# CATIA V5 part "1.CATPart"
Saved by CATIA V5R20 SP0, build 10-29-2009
Part number: Part1
Material "Steel": density 7860 kg/m3, Young's modulus 2e+11 Pa, Poisson ratio 0.266, thermal expansion 1.17e-05 1/K
Bounding box of the stored display mesh (mm): x -9.62 to 87.685, y -20.777 to 20.777, z -26.228 to 2
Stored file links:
  E:\Ehsan\Amoozesh\CATIA\CATIA Course\Advanced\Videos\Session-14\1.CATPart
  D:\CATIA V5R20\B20\intel_a\startup\materials\Catalog.CATMaterial
  D:\CATIA V5R20\B20\intel_a\resources\graphic\figures\CATIA_EnvironmentMap_Potsdamer_512x512.jpg
  D:\CATIA V5R20\B20\intel_a\resources\graphic\figures\CATIA_EnvironmentMap_DSBlack_512x512.jpg
  D:\CATIA V5R20\B20\intel_a\resources\graphic\figures\CATIA_EnvironmentMap_Default_512x512.jpg
  D:\CATIA V5R20\B20\intel_a\resources\graphic\figures\CATIA_EnvironmentMap_DSYellow_512x512.jpg
  D:\CATIA V5R20\B20\intel_a\resources\graphic\figures\CATIA_EnvironmentMap_DSRed_512x512.jpg
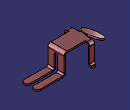
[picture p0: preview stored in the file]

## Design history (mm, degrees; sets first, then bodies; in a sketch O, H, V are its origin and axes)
SheetMetalParameters1: Thickness 2, BendRadius 2, KFactor 0.325257 {= log(min(100,max(20*SheetMetalParameters1.BendRadius,SheetMetalParameters1.Thickness)/SheetMetalParameters1.Thickness))/log(100)/2}, ReliefRadialLength 1, ReliefAxialLength 2, MinimumBendRadius 0
Body1 (main body), material "Steel"
  Sketch1 on xy-plane, origin (0, 0, 0), H (0, 1, 0), V (-1, 0, 0)
    arc A1 centre (0, 0) radius 12.5 from (3.5, -12) to (-3.5, -12) ccw
    point P1 (40, -19.25)
    point P2 (-3.5, -12)
    line L1 (-3.5, -12) -> (-3.5, -16)
    point P3 (-3.5, -16)
    line L2 (-3.5, -16) -> (-40, -16)
    point P4 (-40, -16)
    arc A2 centre (-40, -19.25) radius 3.25 from (-40, -16) to (-40, -22.5) ccw
    point P5 (-40, -19.25)
    point P6 (-40, -22.5)
    line L3 (-40, -22.5) -> (-11, -22.5)
    point P7 (-11, -22.5)
    line L4 (-11, -22.5) -> (-11, -106)
    point P8 (-11, -106)
    arc A3 centre (-6.75, -106) radius 4.25 from (-11, -106) to (-2.5, -106) ccw
    point P10 (-2.5, -106)
    line L5 (-2.5, -106) -> (-2.5, -56)
    point P11 (-2.5, -56)
    arc A4 centre (0, -56) radius 2.5 from (-2.5, -56) to (2.5, -56) cw
    point P13 (2.5, -56)
    point P14 (2.5, -56)
    point P15 (2.5, -106)
    point P16 (11, -106)
    point P17 (11, -22.5)
    point P18 (40, -22.5)
    point P19 (40, -16)
    point P20 (3.5, -16)
    point P21 (3.5, -12)
    line L6 (2.5, -106) -> (2.5, -56)
    point P22 (6.75, -106)
    arc A5 centre (6.75, -106) radius 4.25 from (11, -106) to (2.5, -106) cw
    line L7 (11, -22.5) -> (11, -106)
    line L8 (40, -22.5) -> (11, -22.5)
    arc A6 centre (40, -19.25) radius 3.25 from (40, -16) to (40, -22.5) cw
    line L9 (3.5, -16) -> (40, -16)
    line L10 (3.5, -12) -> (3.5, -16)
    radius A1 = 12.5
    distance P5 V = 40
    distance L10 L1 = 7
    distance L9 L8 = 6.5
    distance L6 L7 = 8.5
    radius A4 = 2.5
    length L6 = 50
    distance P22 H = 106
    distance H L9 = 16
    vertical: L1 V, L4 V
    horizontal: L2 H
    tangency: A2 L2, L3 A2, A3 L4, L5 A3, A4 L5
    symmetry: P11 P14 V, P10 P15 V, P8 P16 V, P7 P17 V, P6 P18 V, P4 P19 V, P3 P20 V, P2 P21 V, L5 L6 V, A3 A5 V, L4 L7 V, L3 L8 V, A2 A6 V, L2 L9 V, L1 L10 V
    coincidence: P13 P14
  Wall1: Thickness 2, Profile Sketch1
  FlatBend1: FlatBendAngle 90, FlatBendAngle 90, FlatBendAngle 90, Axis Sketch6, FixedPoint vertex [face of Wall1 | face of Wall1 | face of Wall1], FlatBendKFactor 0.325257 {= log(min(100,max(20*FlatBend1.FlatBendRadius,SheetMetalParameters1.Thickness)/SheetMetalParameters1.Thickness))/log(100)/2}, FlatBendKFactor 0.325257 {= log(min(100,max(20*FlatBend1.FlatBendRadius,SheetMetalParameters1.Thickness)/SheetMetalParameters1.Thickness))/log(100)/2}, FlatBendKFactor 0.325257 {= log(min(100,max(20*FlatBend1.FlatBendRadius,SheetMetalParameters1.Thickness)/SheetMetalParameters1.Thickness))/log(100)/2}, FlatBendRadius 2 {= SheetMetalParameters1.BendRadius}, FlatBendRadius 2 {= SheetMetalParameters1.BendRadius}, FlatBendRadius 2 {= SheetMetalParameters1.BendRadius}
  FlatBend2: Angle 90, Axis Sketch5, FixedPoint vertex [face of Wall1 | face of Wall1 | face of Wall1], KFactor 0.325257 {= log(min(100,max(20*FlatBend2.FlatBendRadius,SheetMetalParameters1.Thickness)/SheetMetalParameters1.Thickness))/log(100)/2}, Radius 2 {= SheetMetalParameters1.BendRadius}
  FlatBend3: Angle 90, Axis Sketch4, FixedPoint vertex [face of FlatBend1 | face of FlatBend1 | face of Wall1 | face of Wall1], KFactor 0.325257 {= log(min(100,max(20*FlatBend3.FlatBendRadius,SheetMetalParameters1.Thickness)/SheetMetalParameters1.Thickness))/log(100)/2}, Radius 2 {= SheetMetalParameters1.BendRadius}
  FlatBend4: Angle 90, Axis Sketch3, FixedPoint vertex [face of FlatBend1 | face of FlatBend1 | face of Wall1 | face of Wall1], KFactor 0.325257 {= log(min(100,max(20*FlatBend4.FlatBendRadius,SheetMetalParameters1.Thickness)/SheetMetalParameters1.Thickness))/log(100)/2}, Radius 2 {= SheetMetalParameters1.BendRadius}
  FlatBend5: Angle 150, Axis Sketch2, FixedPoint vertex [face of FlatBend1 | face of FlatBend1 | face of Wall1 | face of Wall1], KFactor 0.325257 {= log(min(100,max(20*FlatBend5.FlatBendRadius,SheetMetalParameters1.Thickness)/SheetMetalParameters1.Thickness))/log(100)/2}, Radius 2 {= SheetMetalParameters1.BendRadius}
  Sketch2 on face of Wall1, origin (0, 0, 2), H (1, 0, 0), V (0, 1, 0)
    line L1 (14.258, 5.8017) -> (14.258, -4.9461)
    vertical: L1 V
  Sketch3 on face of Wall1, origin (0, 17.1921, 0), H (-1, 0, 0), V (0, 0, 1)
    line L1 (-25.1719, -24.2278) -> (-13.2252, -24.2278)
    reference projected line E1 (-47.6828, -24.2278) -> (-83.4453, -24.2278) from edge [face of Wall1 | face of Wall1]
    horizontal: L1 H
    coincidence: L1 E1
  Sketch4 on face of Wall1, origin (0, -17.1921, 0), H (1, 0, 0), V (0, 0, 1)
    line L1 (13.3653, -24.2278) -> (24.4353, -24.2278)
    reference projected line E1 (83.4453, -24.2278) -> (47.6828, -24.2278) from edge [face of Wall1 | face of Wall1]
    horizontal: L1 H
    coincidence: L1 E1
  Sketch5 on face of Wall1, origin (51.2769, 0, 0), H (0, 1, 0), V (0, 0, 1)
    line L1 (-19.6972, -24.3095) -> (18.1239, -24.3095)
    horizontal: L1 H
  Sketch6 on face of Wall1, origin (0, 0, 2), H (1, 0, 0), V (0, 1, 0)
    line L1 (14.1579, 15.2739) -> (23.4254, 15.2739)
    point P1 (14.1579, 15.2739)
    point P2 (23.4254, 15.2739)
    line L2 (49.3586, 13.7374) -> (49.3586, -13.6262)
    point P5 (23.4254, -15.2739)
    point P6 (14.1579, -15.2739)
    line L3 (14.1579, -15.2739) -> (23.4254, -15.2739)
    horizontal: L1 H
    vertical: L2 V
    symmetry: P2 P5 H, P1 P6 H, L1 L3 H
